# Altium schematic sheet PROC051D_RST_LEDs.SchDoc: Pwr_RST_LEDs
size 431 x 279 mm; Date: Not shown in title block; ApprovedBy: Not shown in title block; CheckedBy: Not shown in title block; Author: Not shown in title block; CompanyName: Not shown in title block; Engineer: Not shown in title block; Organization: Not shown in title block; Address1: Not shown in title block; Address2: Not shown in title block; Address3: Not shown in title block; Address4: Not shown in title block; DocumentNumber: 8; Revision: Use project parameter SCH_Rev; SheetNumber: 8; SheetTotal: 16; PageSetup: Record=PageOptions¦CenterHorizontal=True¦CenterVertical=True¦PrintScale=1.00¦XCorrection=1.00¦YCorrection=1.00¦PrintKind=0¦BorderSize=5000000¦LeftOffset=0¦BottomOffset=0¦Orientation=2¦PaperLength=1000¦PaperWidth=1000¦Scale=100¦PaperSource=15¦PrintQuality=600¦MediaType=1¦DitherType=10¦PaperKind=Letter¦PrintScaleMode=1
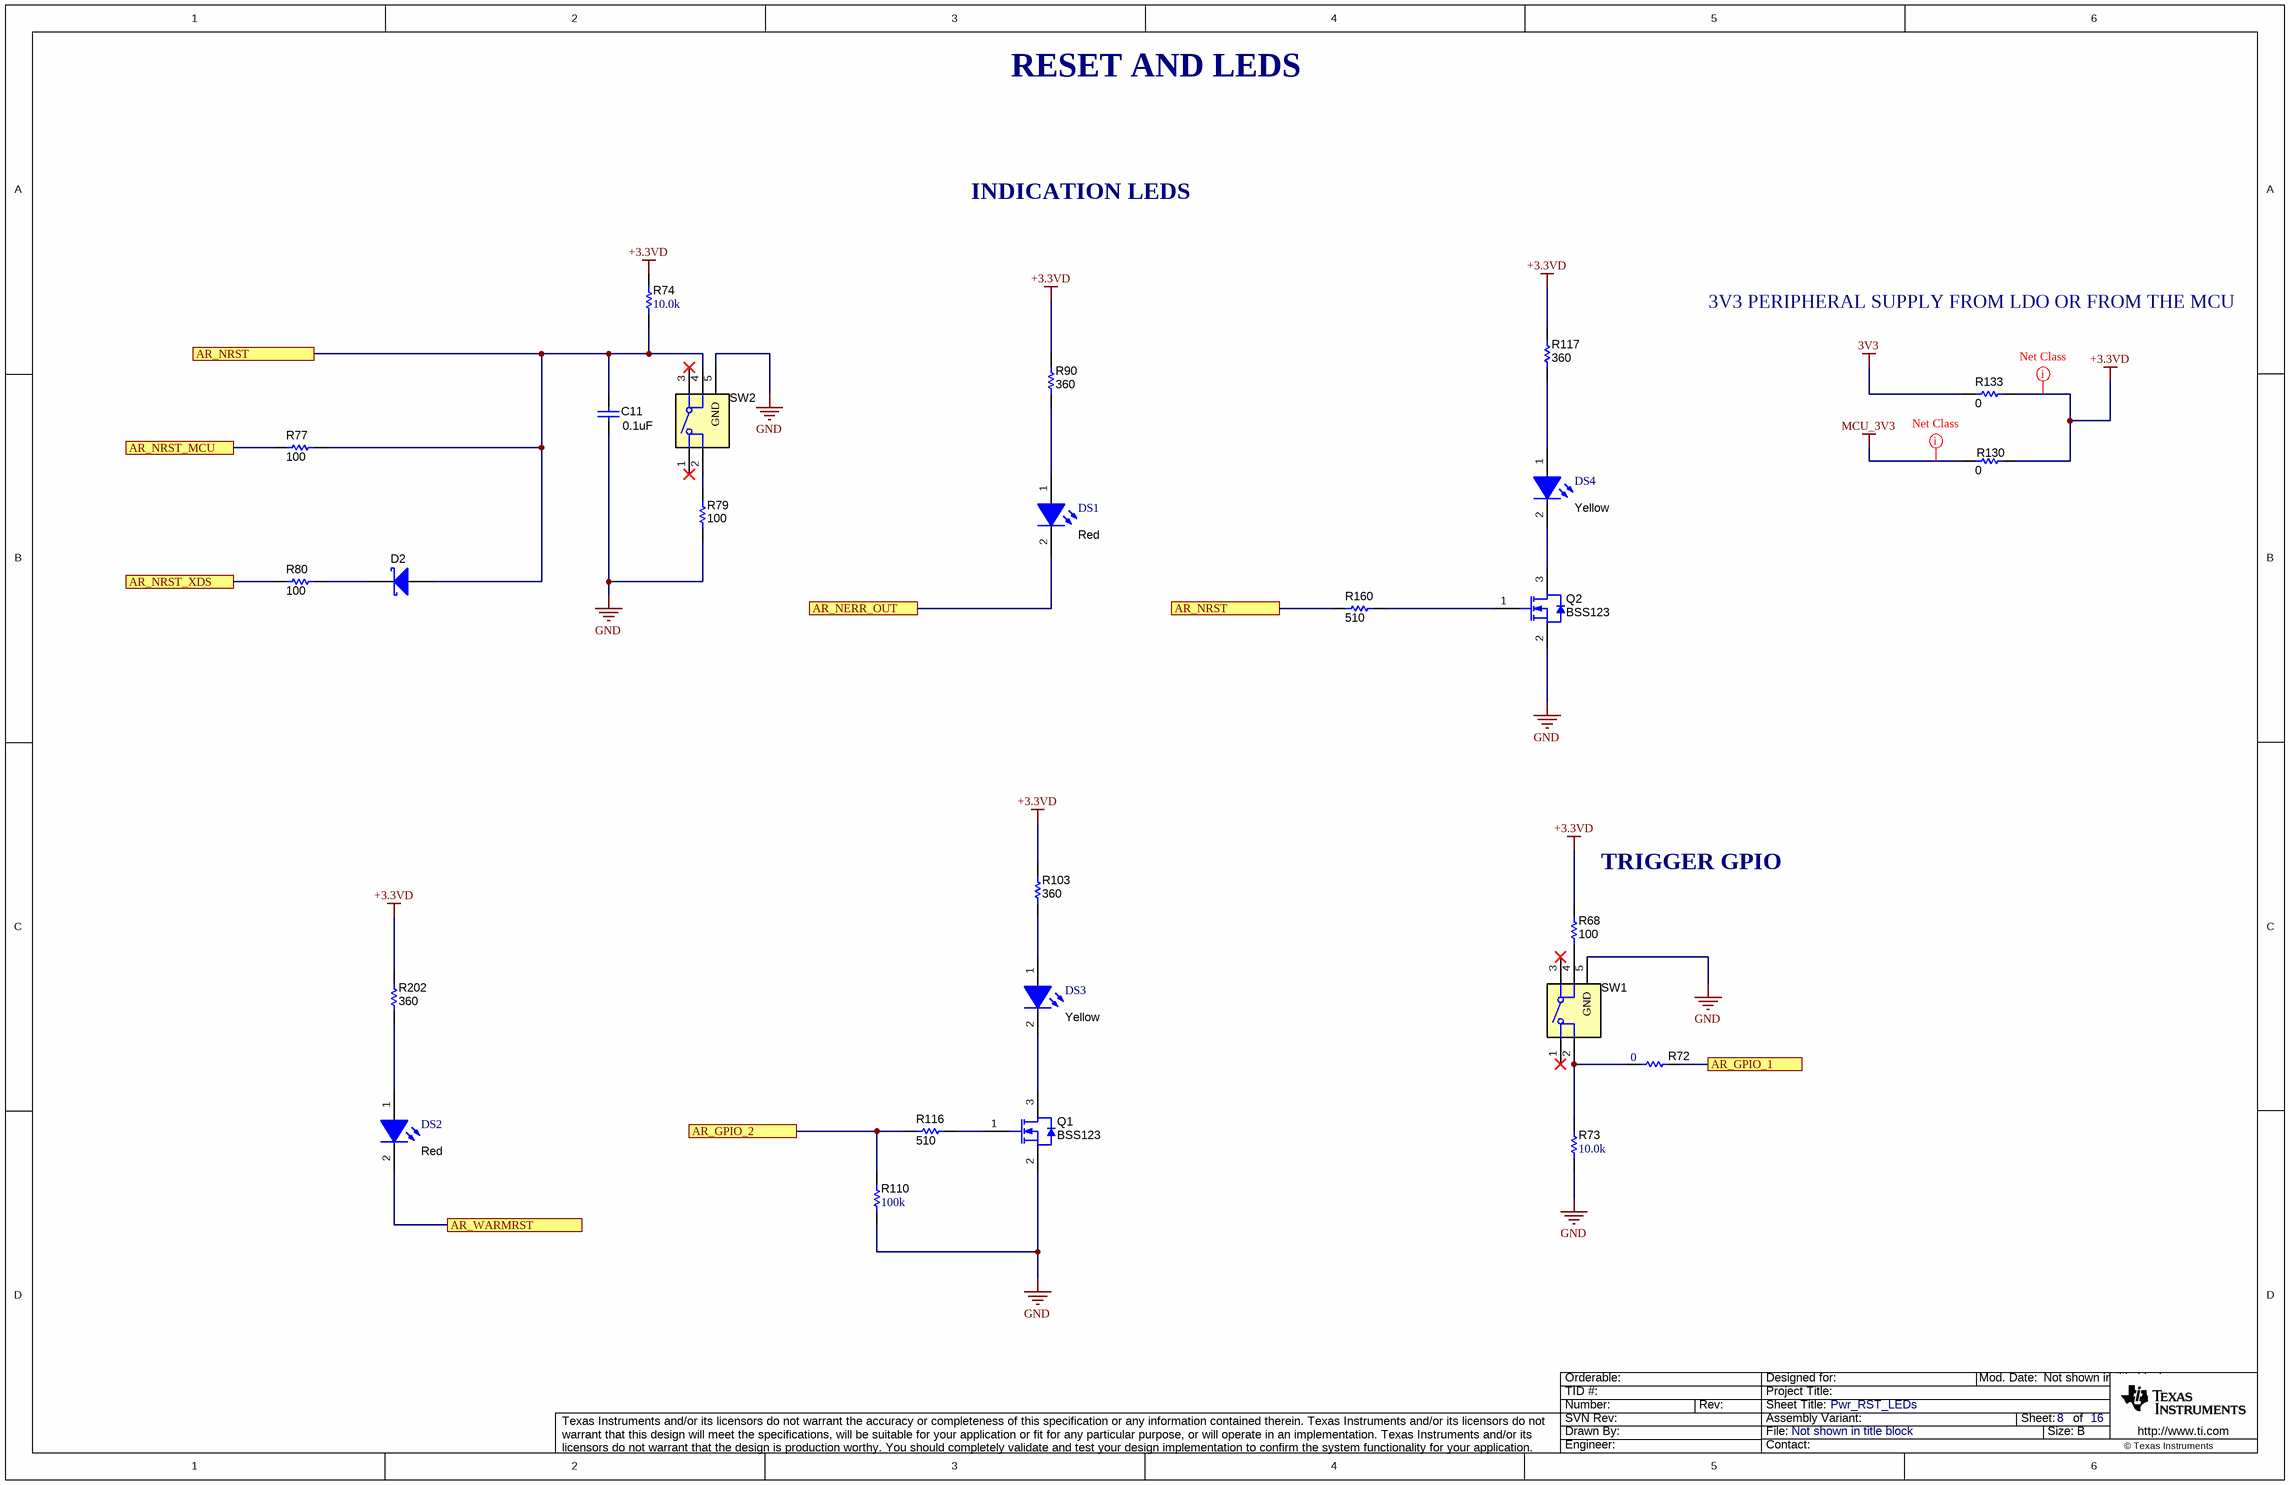
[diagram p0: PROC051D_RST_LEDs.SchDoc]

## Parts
C11  ValueDisplayed: 0.1uF  [0402L]  (hidden comment: GCM155R71C104KA55D)
D2  SMS3923-040LF  [SOD-882]  (value not drawn)
DS1  value Red  [LS L29K_Red]  (hidden comment: LS L29K-G1J2-1-Z)
DS2  value Red  [LS L29K_Red]  (hidden comment: LS L29K-G1J2-1-Z)
DS3  value Yellow  [SML-E1_Yellow]  (hidden comment: SML-E12Y8WT86)
DS4  value Yellow  [SML-E1_Yellow]  (hidden comment: SML-E12Y8WT86)
Q1  BSS123  [SOT-23]
Q2  BSS123  [SOT-23]
R68  ValueDisplayed: 100  [0402L]  (hidden comment: ERJ-2GEJ101X)
R72  ValueDisplayed: 0  [0201_Silk]  (hidden comment: CRCW02010000Z0ED)
R73  ValueDisplayed: 10.0k  [0402L]  (hidden comment: CRCW040210K0FKED)
R74  ValueDisplayed: 10.0k  [0402L]  (hidden comment: CRCW040210K0FKED)
R77  ValueDisplayed: 100  [0402L]  (hidden comment: ERJ-2GEJ101X)
R79  ValueDisplayed: 100  [0402L]  (hidden comment: ERJ-2GEJ101X)
R80  ValueDisplayed: 100  [0402L]  (hidden comment: ERJ-2GEJ101X)
R90  ValueDisplayed: 360  [0402L]  (hidden comment: ERJ-2GEJ361X)
R103  ValueDisplayed: 360  [0402L]  (hidden comment: ERJ-2GEJ361X)
R110  ValueDisplayed: 100k  [0402L]  (hidden comment: CRCW0402100KFKED)
R116  ValueDisplayed: 510  [0402L]  (hidden comment: ERJ-2GEJ511X)
R117  ValueDisplayed: 360  [0402L]  (hidden comment: ERJ-2GEJ361X)
R130  ValueDisplayed: 0  [0603]  (hidden comment: MCT06030Z0000ZP500)
R133  ValueDisplayed: 0  [0603]  (hidden comment: MCT06030Z0000ZP500)
R160  ValueDisplayed: 510  [0402L]  (hidden comment: ERJ-2GEJ511X)
R202  ValueDisplayed: 360  [0402L]  (hidden comment: ERJ-2GEJ361X)
SW1  KMR243GLFG  [SW_KMR243GLFG]  (value not drawn)
SW2  KMR243GLFG  [SW_KMR243GLFG]  (value not drawn)

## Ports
AR_GPIO_1, AR_GPIO_2, AR_NERR_OUT, AR_NRST, AR_NRST_MCU, AR_NRST_XDS, AR_WARMRST

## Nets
3V3: R133.1
+3.3VD: R68.2 R74.2 R90.2 R103.2 R117.2 R130.2 R133.2 R202.2
GND: C11.1 Q1.2(S) Q2.2(S) R73.1 R79.1 R110.1 SW1.5(GND) SW2.5(GND)
MCU_3V3: R130.1
AR_GPIO_1: R72.2 ; port AR_GPIO_1
AR_GPIO_2: R110.2 R116.1 ; port AR_GPIO_2
AR_NERR_OUT: DS1.2(K) ; port AR_NERR_OUT
AR_NRST: C11.2 D2.2(A) R74.1 R77.2 R160.1 SW2.4 ; port AR_NRST
AR_NRST_MCU: R77.1 ; port AR_NRST_MCU
AR_NRST_XDS: R80.1 ; port AR_NRST_XDS
AR_WARMRST: DS2.2(K) ; port AR_WARMRST
NetD2_1: D2.1(K) R80.2
NetDS1_1: DS1.1(A) R90.1
NetDS2_1: DS2.1(A) R202.1
NetDS3_1: DS3.1(A) R103.1
NetDS3_2: DS3.2(K) Q1.3(D)
NetDS4_1: DS4.1(A) R117.1
NetDS4_2: DS4.2(K) Q2.3(D)
NetQ1_1: Q1.1(G) R116.2
NetQ2_1: Q2.1(G) R160.2
NetR68_1: R68.1 SW1.4
NetR72_1: R72.1 R73.2 SW1.2
NetR79_2: R79.2 SW2.2

Not connected (* = marked no-connect by the designer): SW1 1* 3*; SW2 1* 3*

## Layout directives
net class PWR: +3.3VD, MCU_3V3

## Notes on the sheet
- RESET AND LEDS
- INDICATION LEDS
- 3V3 PERIPHERAL SUPPLY FROM LDO OR FROM THE MCU
- (near R68) TRIGGER GPIO

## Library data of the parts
C11 = CMP-0006351-2: CAP, CERM, 0.1 uF, 16 V, +/- 10%, X7R, 0402; Manufacturer: MuRata; TaMin_C: -55°C; Polarized: N; SizeAreaWB_mm2: 3; Value1: Unknown; U/M: EA; Value: 0.1uF; TaMax_C: 125°C; SizeZ_mm: 0.6; SizeX_mm: 1; SizeY_mm: 0.5; Cap_Case: 0402; Value2: 16V; Cap_F: 100nF; AEC Category: Q200
D2 = CMP-0078187-2: Diode, Schottky,  V, 0.01 A, SOD-882; Manufacturer: Skyworks Solutions; SizeAreaWB_mm2: 3.2; SizeArea_mm2: 0.6; AEC Qualified: N; TJmax_C: 150°C; AEC Category: Q101; SizeZ_mm: 0.5; Io_A: 10mA; Vf_V: 340mV; Value2: 0.34V; Value1: 0.01A; SizeX_mm: 1
DS1 DS2 = CMP-0002902-2: LED, Red, SMD; Manufacturer: OSRAM; Io_A: 20mA; Vr_V: 12V; Tjmax_C: 110°C; Value1: W; Angle: 160; Vf_V: 1.8V
DS3 DS4 = CMP-0002977-3: LED, Yellow, SMD; Manufacturer: Rohm; Io_A: 20mA; Power_TotalModule: 54mW; Vr_V: 5V; Tjmax_C: 85°C; Value1: 0.054W; Ir_A: 10µA; Vf_V: 2.2V; LuminousIntensity_IV: 63
Q1 Q2 = CMP-0000947-2: MOSFET, N-CH, 100 V, 0.17 A, SOT-23; Alternate Manufacturer: None; Manufacturer: Fairchild Semiconductor; SizeZ_mm: 1.1; ChType: N; Value2: 1.8 nC; Value1: 1; VdsMax_V: 100V; SizeX_mm: 2.5; SizeY_mm: 3; Vgs_V: 20V; Value: 100V; Rdson45_ohm: 10; SizeArea_mm2: 7.5; AEC Category: Q101; IdsMax_A: 1.7dA; SizeAreaWB_mm2: 14; U/M: EA; QgTyp_nC: 1.8
R68 R77 R79 R80 = CMP-0026993-2: RES, 100, 5%, 0.1 W, AEC-Q200 Grade 0, 0402; Manufacturer: Panasonic; Power_W: 100mW; TempCo: 200 ppm/C; Value_Code: 100R; U/M: EA; Value: 100; EIA_Code: E24; SizeX_mm: 1; SizeY_mm: 0.5; SizeZ_mm: 0.6; Value2: 0.1W; AEC Qualified: Y; AEC Grade: 0; AEC Category: Q200
R72 = CMP-0027008-4: RES, 0, 5%, 0.05 W, 0201; Manufacturer: Vishay-Dale; Power_W: 50mW; TempCo: ppm/C; Value_Code: 0000; Value: 0; EIA_Code: E24; SizeX_mm: 0.6; SizeY_mm: 0.3; SizeZ_mm: 0.26; Value2: 0.05W; SizeArea_mm2: 0.18; AEC Qualified: N; AEC Category: Q200
R73 R74 = CMP-0025958-3: RES, 10.0 k, 1%, 0.063 W, AEC-Q200 Grade 0, 0402; Manufacturer: Vishay-Dale; Power_W: 63mW; TempCo: 100 ppm/C; Value_Code: 10k0; Value: 10.0k; EIA_Code: E96; Res_ohm: 10k; SizeX_mm: 1; SizeY_mm: 0.5; SizeZ_mm: 0.6; Value2: 0.063W; AEC Qualified: Y; VDC_V: 50V; AEC Category: Q200; AEC Grade: 0
R90 R103 R117 R202 = CMP-0078194-1: RES, 360, 5%, 0.1 W, AEC-Q200 Grade 0, 0402; Manufacturer: Panasonic; Value_Code: 360R; SizeArea_mm2: 0.5; AEC Qualified: Y; AEC Category: Q200; Value: 360; SizeZ_mm: 0.6; EIA_Code: E24; TempCo: 200 ppm/C; AEC Grade: 0; Power_W: 100mW; VDC_V: 50V; Value2: 0.1W; U/M: EA; SizeX_mm: 1
R110 = CMP-0025950-3: RES, 100 k, 1%, 0.063 W, AEC-Q200 Grade 0, 0402; Manufacturer: Vishay-Dale; Power_W: 63mW; TempCo: 100 ppm/C; Value: 100k; EIA_Code: E96; SizeX_mm: 1; SizeY_mm: 0.5; SizeZ_mm: 0.6; Value2: 0.063W; AEC Qualified: Y; VDC_V: 50V; AEC Category: Q200; AEC Grade: 0
R116 R160 = CMP-0078212-1: RES, 510, 5%, 0.1 W, AEC-Q200 Grade 0, 0402; Manufacturer: Panasonic; Value_Code: 510R; SizeArea_mm2: 0.5; AEC Qualified: Y; AEC Category: Q200; Value: 510; SizeZ_mm: 0.6; EIA_Code: E24; TempCo: 200 ppm/C; AEC Grade: 0; Power_W: 100mW; VDC_V: 50V; Value2: 0.1W; U/M: EA; SizeX_mm: 1
R130 = CMP-0025884-3: RES, 0, 5%, 0.125 W, 0603; Manufacturer: Vishay/Beyschlag; Power_W: 125mW; TempCo: ppm/C; Value_Code: 0000; U/M: EA; Value: 0; EIA_Code: E24; SizeX_mm: 1.6; SizeY_mm: 0.8; SizeZ_mm: 1; Value2: 0.125W; SizeArea_mm2: 1.28; CompType: Resistor; AEC Qualified: N; AEC Category: Q200
R133 = CMP-0025884-3: RES, 0, 5%, 0.125 W, 0603; Manufacturer: Vishay/Beyschlag; Power_W: 125mW; TempCo: ppm/C; Value_Code: 0000; U/M: EA; Value: 0; EIA_Code: E24; SizeX_mm: 1.6; SizeY_mm: 0.8; SizeZ_mm: 1; Value2: 0.125W; SizeArea_mm2: 1.28; AEC Qualified: N; AEC Category: Q200
SW1 SW2 = CMP-0002325-1: Switch, SPST-NO, Off-Mom, 0.01 A, 32 VDC, SMD; Manufacturer: C&K Components; CurrentRating_mA: 10A; PositionCount: 1; SizeX_mm: 4.6; SizeY_mm: 2.8; SizeZ_mm: 1.9; SizeArea_mm2: 12.88; VDC_V: 32V; SizeAreaWB_mm2: 21.28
